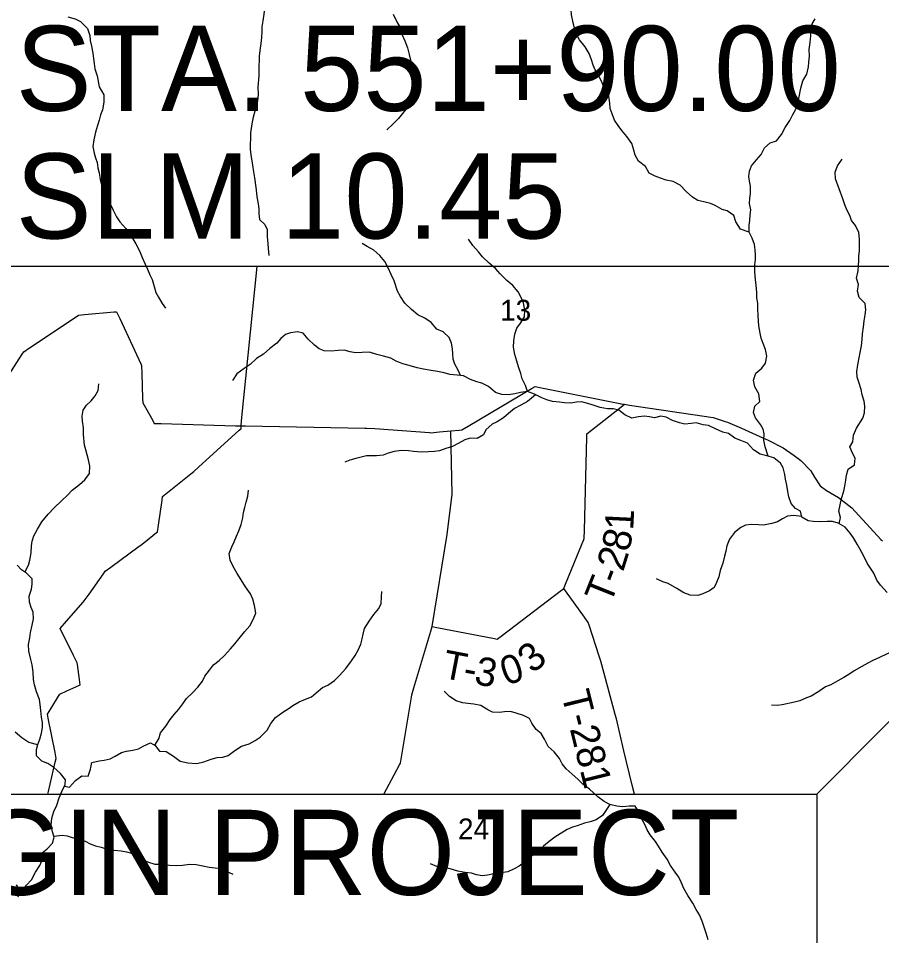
# Model space of a CAD drawing. Extents: x 0 to 34, y 0 to 22.
# Drawn here: x 3.195 to 4.921, y 16.276 to 18.109 of the extents above; entities that cross this region are included whole.
import ezdxf

# ---------------------------------------------------------------- set-up
doc = ezdxf.new("R2010")
doc.units = 0
for name, color, linetype in [('GM_X_County_Road', 7, 'Continuous'), ('GM_X_Minor_River', 7, 'Continuous'), ('GM_X_Section_Text', 7, 'Continuous'), ('GM_X_Township_Road', 7, 'Continuous'), ('GM_X_Township_Road_Text', 7, 'Continuous'), ('SH_Text', 7, 'Continuous')]:
    doc.layers.add(name, color=color, linetype=linetype)

msp = doc.modelspace()

# ---------------------------------------------------------------- linework, layer by layer
at = {"layer": 'GM_X_County_Road'}
msp.add_lwpolyline([(3.2543, 16.5585), (3.2555, 16.5637), (3.269, 16.6223), (3.2708, 16.6302), (3.2685, 16.6419), (3.2548, 16.7107), (3.2533, 16.7184), (3.2598, 16.7288), (3.2757, 16.7543), (3.2784, 16.7586), (3.292, 16.7648), (3.3102, 16.7731), (3.3186, 16.7769), (3.3172, 16.7877), (3.3133, 16.8175), (3.3129, 16.8209), (3.3054, 16.8357), (3.2785, 16.8894), (3.2914, 16.9045), (3.3246, 16.9421), (3.3269, 16.9447), (3.3365, 16.9582), (3.3655, 16.999), (3.369, 17.004), (3.3802, 17.0123), (3.4366, 17.054), (3.44, 17.0564), (3.4524, 17.0663), (3.4681, 17.0788), (3.4733, 17.083), (3.4753, 17.0962), (3.4825, 17.1458), (3.4836, 17.1533), (3.4933, 17.1611), (3.5402, 17.1987), (3.5462, 17.2034), (3.5553, 17.2118), (3.6367, 17.2861), (3.6403, 17.2893), (3.6407, 17.2946), (3.6415, 17.3045), (3.6723, 17.6129)], dxfattribs=at)
at = {"layer": 'GM_X_Minor_River'}
for points in [[(3.6962, 18.2358), (3.6942, 18.2156), (3.694, 18.1932), (3.6925, 18.1838), (3.692, 18.1739), (3.6931, 18.1637), (3.693, 18.1542), (3.6888, 18.1402), (3.6872, 18.1292), (3.6856, 18.1167), (3.6836, 18.1034), (3.682, 18.092), (3.6816, 18.0826), (3.6815, 18.0701), (3.6799, 18.0583), (3.6779, 18.0443), (3.6767, 18.0333), (3.6766, 18.0238), (3.6762, 18.0143), (3.676, 17.9939), (3.6736, 17.9711)], [(4.3661, 17.9698), (4.3612, 17.983), (4.3556, 17.9929), (4.3485, 18.0058), (4.344, 18.0153), (4.3407, 18.0256), (4.3362, 18.0385), (4.3284, 18.0515), (4.3167, 18.0656), (4.3119, 18.0755), (4.3067, 18.0888), (4.3038, 18.1028), (4.3008, 18.1154), (4.3005, 18.1248), (4.2994, 18.1358), (4.2995, 18.1487), (4.3008, 18.1616), (4.3035, 18.1749)], [(3.2943, 18.1116), (3.3086, 18.1074), (3.3196, 18.1024), (3.3335, 18.0886), (3.3379, 18.0742), (3.339, 18.0643), (3.3412, 18.0529), (3.3441, 18.0393), (3.3456, 18.0286), (3.3466, 18.0184), (3.3481, 18.0078), (3.3529, 17.9941), (3.3566, 17.9717)], [(3.9444, 18.1173), (3.9522, 18.1005), (3.9582, 18.0906), (3.9619, 18.0773), (3.9675, 18.0637), (3.9734, 18.0496), (3.9764, 18.0363), (3.9793, 18.0253), (3.9815, 18.0158), (3.9871, 18.0021), (3.9935, 17.9884), (3.9902, 17.9705)], [(4.7596, 17.969), (4.7635, 17.9837), (4.7715, 17.9973), (4.775, 18.0117), (4.7754, 18.0212), (4.7767, 18.033), (4.7764, 18.0462), (4.778, 18.0603), (4.7792, 18.0735), (4.7789, 18.0868), (4.782, 18.0974), (4.7881, 18.1076)], [(3.3566, 17.9717), (3.3662, 17.9558), (3.3662, 17.9414), (3.3631, 17.9259), (3.3597, 17.9157), (3.3566, 17.9054), (3.3531, 17.8945), (3.3497, 17.8812), (3.3462, 17.866), (3.3439, 17.8528), (3.3469, 17.8395), (3.3495, 17.83), (3.3525, 17.8205), (3.3543, 17.8099), (3.3566, 17.8), (3.3588, 17.7868), (3.3614, 17.7769), (3.3648, 17.7674), (3.3697, 17.7572), (3.3742, 17.7477), (3.3847, 17.7256), (3.3914, 17.712), (3.3978, 17.7021), (3.4103, 17.6888), (3.4178, 17.6778), (3.4238, 17.6679), (3.4298, 17.6584), (3.4377, 17.644), (3.4426, 17.631), (3.4486, 17.6174), (3.4531, 17.6075), (3.4583, 17.5961), (3.4625, 17.5866), (3.4666, 17.573), (3.4703, 17.5608), (3.4756, 17.5513), (3.4827, 17.5392), (3.4895, 17.5297)], [(3.6736, 17.9711), (3.6749, 17.9566), (3.6734, 17.9437), (3.6711, 17.9338), (3.668, 17.9229), (3.6649, 17.9111), (3.6622, 17.8979), (3.6595, 17.8801), (3.6591, 17.8672), (3.6587, 17.8577), (3.6586, 17.8471), (3.6597, 17.8361), (3.6634, 17.8156), (3.6653, 17.802), (3.6671, 17.7902), (3.6704, 17.7663), (3.6719, 17.7519), (3.6745, 17.7382), (3.676, 17.728), (3.6759, 17.7185), (3.677, 17.7068), (3.6876, 17.6965), (3.6925, 17.6866), (3.6928, 17.6722), (3.6939, 17.6586), (3.6946, 17.6487), (3.6961, 17.6351)], [(3.9902, 17.9705), (3.9851, 17.9513), (3.9775, 17.9384), (3.971, 17.9286), (3.9634, 17.9188), (3.9551, 17.9089), (3.9448, 17.8976), (3.9319, 17.8859)], [(4.6563, 17.6816), (4.639, 17.6877), (4.6296, 17.7022), (4.6254, 17.7147), (4.6122, 17.7242), (4.6024, 17.7265), (4.5884, 17.7349), (4.5786, 17.7387), (4.5658, 17.7422), (4.5537, 17.7445), (4.5427, 17.7514), (4.5299, 17.7624), (4.5182, 17.7754), (4.5043, 17.7826), (4.4899, 17.7857), (4.4786, 17.7891), (4.468, 17.7934), (4.4559, 17.7995), (4.4488, 17.8128), (4.4348, 17.823), (4.428, 17.8356), (4.4258, 17.8451), (4.4217, 17.8587), (4.4119, 17.8728), (4.4014, 17.8846), (4.3942, 17.8945), (4.3867, 17.9051), (4.3822, 17.9176), (4.3784, 17.9283), (4.3773, 17.9389), (4.3755, 17.9529), (4.3661, 17.9698)], [(4.6942, 17.2341), (4.688, 17.2524), (4.6854, 17.266), (4.6859, 17.2785), (4.684, 17.288), (4.6787, 17.2975), (4.6686, 17.3108), (4.6648, 17.3214), (4.6675, 17.3339), (4.6774, 17.3434), (4.6752, 17.3582), (4.6673, 17.3722), (4.6647, 17.3855), (4.6697, 17.3999), (4.6814, 17.4097), (4.689, 17.4195), (4.6914, 17.4339), (4.6891, 17.4472), (4.6843, 17.4593), (4.6801, 17.4696), (4.6779, 17.4795), (4.6757, 17.4943), (4.675, 17.5041), (4.6743, 17.5143), (4.6736, 17.5291), (4.6732, 17.5397), (4.6717, 17.55), (4.6714, 17.561), (4.6703, 17.5754), (4.6688, 17.5868), (4.6674, 17.6023), (4.6678, 17.616), (4.669, 17.6266), (4.6687, 17.636), (4.6679, 17.6463), (4.6668, 17.6569), (4.6623, 17.6694), (4.6563, 17.6816), (4.6564, 17.6952), (4.6572, 17.7047), (4.658, 17.7161), (4.6595, 17.7259), (4.6569, 17.7388), (4.6573, 17.7494), (4.6585, 17.7589), (4.6586, 17.7733), (4.6567, 17.7832), (4.6556, 17.7927), (4.6568, 17.8036), (4.6606, 17.8139), (4.6709, 17.826), (4.68, 17.8365), (4.6865, 17.8502), (4.6982, 17.86), (4.7107, 17.8641), (4.721, 17.8766), (4.7279, 17.8906), (4.7377, 17.9045), (4.7427, 17.9151), (4.7492, 17.9273), (4.753, 17.9371), (4.7557, 17.9488), (4.7596, 17.969)], [(4.8361, 17.0989), (4.8388, 17.1112), (4.8355, 17.1241), (4.8378, 17.1369), (4.8405, 17.1494), (4.8451, 17.1638), (4.8474, 17.1737), (4.8497, 17.1862), (4.8505, 17.196), (4.8543, 17.2078), (4.8665, 17.2168), (4.868, 17.2297), (4.8624, 17.2396), (4.8575, 17.2529), (4.8636, 17.2627), (4.8648, 17.2759), (4.8709, 17.2896), (4.8831, 17.31), (4.8865, 17.3202), (4.8873, 17.3339), (4.8862, 17.3441), (4.8821, 17.3562), (4.8799, 17.3672), (4.8754, 17.3817), (4.872, 17.3919), (4.8713, 17.4029), (4.8736, 17.4166), (4.876, 17.4306), (4.8783, 17.4412), (4.8806, 17.4544), (4.8818, 17.4669), (4.8826, 17.4783), (4.8849, 17.4919), (4.8861, 17.5041), (4.888, 17.5166), (4.8892, 17.526), (4.8881, 17.5389), (4.876, 17.5511), (4.8727, 17.5636), (4.875, 17.5769), (4.8709, 17.5898), (4.8743, 17.6042), (4.8747, 17.6152), (4.8752, 17.6247), (4.8756, 17.6345), (4.8767, 17.6444), (4.8768, 17.6546), (4.8765, 17.6682), (4.8757, 17.6808), (4.869, 17.6948), (4.8607, 17.7051), (4.8573, 17.7146), (4.8521, 17.7248), (4.8476, 17.7358), (4.8431, 17.748), (4.8285, 17.7878), (4.8278, 17.8011), (4.8327, 17.814), (4.8419, 17.8272)], [(4.2133, 17.3633), (4.2092, 17.3751), (4.2021, 17.3887), (4.1994, 17.3993), (4.1953, 17.4126), (4.1916, 17.424), (4.1875, 17.4369), (4.1849, 17.4517), (4.1857, 17.4642), (4.188, 17.4775), (4.1915, 17.49), (4.1987, 17.4998), (4.2067, 17.5123), (4.2079, 17.5259), (4.2049, 17.54), (4.2008, 17.5498), (4.1944, 17.562), (4.1838, 17.5749), (4.1714, 17.5848), (4.1582, 17.5985), (4.1491, 17.6088), (4.1363, 17.6194), (4.1231, 17.6324), (4.1152, 17.6419), (4.1035, 17.6548), (4.0953, 17.6677)], [(4.0792, 17.395), (4.0746, 17.4055), (4.0675, 17.418), (4.0645, 17.4279), (4.0638, 17.4385), (4.0634, 17.4484), (4.0612, 17.4594), (4.0567, 17.4711), (4.0443, 17.4822), (4.0318, 17.4875), (4.0205, 17.5008), (4.0081, 17.5096), (3.9941, 17.5161), (3.9813, 17.5271), (3.9681, 17.5393), (3.9594, 17.553), (3.9534, 17.5636), (3.9467, 17.5841), (3.9407, 17.597), (3.9347, 17.6103), (3.9279, 17.6228), (3.9181, 17.6346), (3.9057, 17.6453), (3.8925, 17.6529), (3.8826, 17.6586)], [(4.0723, 17.3956), (4.0576, 17.3968), (4.0466, 17.4007), (4.033, 17.4034), (4.0202, 17.4053), (4.005, 17.408), (3.9922, 17.4107), (3.9763, 17.4153), (3.9635, 17.4184), (3.9506, 17.4238), (3.9397, 17.4295), (3.9249, 17.4337), (3.9121, 17.4368), (3.897, 17.4414), (3.8826, 17.4411), (3.8694, 17.4407), (3.8584, 17.4427), (3.8467, 17.4454), (3.8342, 17.445), (3.8206, 17.4436), (3.8066, 17.4444), (3.7967, 17.4486), (3.7869, 17.4554), (3.7745, 17.4676), (3.7647, 17.4798), (3.753, 17.4821), (3.7394, 17.4806), (3.7295, 17.4772), (3.72, 17.4693), (3.7121, 17.4595), (3.6976, 17.4489), (3.6851, 17.438), (3.6715, 17.4293), (3.6589, 17.4172), (3.6464, 17.4093), (3.632, 17.3984), (3.6233, 17.3851)], [(4.9321, 16.9618), (4.9185, 16.9763), (4.9114, 16.9862), (4.9054, 17.0002), (4.899, 17.0101), (4.8922, 17.0204), (4.8855, 17.034), (4.8776, 17.0485), (4.8719, 17.0583), (4.8644, 17.0705), (4.858, 17.08), (4.8478, 17.0922), (4.8339, 17.1002), (4.8225, 17.1036), (4.8119, 17.1033), (4.7968, 17.103), (4.784, 17.1034), (4.7741, 17.1046), (4.7617, 17.1118), (4.7587, 17.1243), (4.7489, 17.1297), (4.7402, 17.1396), (4.7357, 17.1525), (4.7335, 17.1635), (4.7313, 17.176), (4.729, 17.1881), (4.7272, 17.1976), (4.7238, 17.2105), (4.7189, 17.22), (4.7054, 17.2307), (4.6914, 17.2349), (4.6778, 17.238), (4.6649, 17.2464), (4.6529, 17.2601), (4.6397, 17.2654), (4.6272, 17.27), (4.6151, 17.2792), (4.6038, 17.2822), (4.5891, 17.2887), (4.5747, 17.2949), (4.5645, 17.2964), (4.5505, 17.3003), (4.5403, 17.2995), (4.5274, 17.2981), (4.5172, 17.3008), (4.5032, 17.305), (4.49, 17.3119), (4.4798, 17.3138), (4.467, 17.3108), (4.4571, 17.3127), (4.4469, 17.3139), (4.4352, 17.3124), (4.4219, 17.3098), (4.4076, 17.3163), (4.3955, 17.3258), (4.3842, 17.3282), (4.3728, 17.3286), (4.3581, 17.3313), (4.3445, 17.3355), (4.3339, 17.339), (4.3207, 17.3424), (4.3108, 17.3417), (4.2995, 17.3395), (4.287, 17.3403), (4.2772, 17.3418), (4.2628, 17.343), (4.2518, 17.3465), (4.2416, 17.3507), (4.2273, 17.3575), (4.2133, 17.3633), (4.1989, 17.3614), (4.1876, 17.3585), (4.1747, 17.3562), (4.1615, 17.357), (4.149, 17.3609), (4.135, 17.373), (4.1218, 17.3795), (4.112, 17.3826), (4.0988, 17.3872), (4.0848, 17.3945), (4.0723, 17.3956)], [(3.2084, 17.0023), (3.2152, 17.0163), (3.2183, 17.0261), (3.221, 17.0409), (3.2218, 17.0545), (3.223, 17.064), (3.2264, 17.0746), (3.2333, 17.0882), (3.2424, 17.1026), (3.2546, 17.1181), (3.2671, 17.1306), (3.2815, 17.1445), (3.2937, 17.1559), (3.3028, 17.1657), (3.3176, 17.177), (3.3278, 17.1868), (3.3377, 17.1993), (3.3381, 17.2141), (3.3352, 17.2266), (3.3326, 17.2368), (3.3303, 17.2463), (3.3277, 17.2562), (3.3255, 17.2774), (3.3256, 17.2907), (3.3233, 17.304), (3.323, 17.3138), (3.3246, 17.326), (3.3314, 17.3358), (3.3409, 17.3445), (3.3489, 17.3547), (3.3546, 17.3653), (3.3562, 17.3785)], [(4.229, 17.3567), (4.2132, 17.3432), (4.2, 17.336), (4.1871, 17.3293), (4.1753, 17.3191), (4.1651, 17.3108), (4.1522, 17.3025), (4.1423, 17.298), (4.1298, 17.2866), (4.1252, 17.2764), (4.1123, 17.2693), (4.0987, 17.2701), (4.0877, 17.2667), (4.0741, 17.2592), (4.0631, 17.2535), (4.0498, 17.249), (4.0373, 17.2445), (4.0271, 17.243), (4.015, 17.2423), (4.001, 17.242), (3.9851, 17.2432), (3.9749, 17.2447), (3.9613, 17.2452), (3.9465, 17.243), (3.9344, 17.2396), (3.9246, 17.2362), (3.911, 17.2347), (3.9007, 17.2344), (3.8909, 17.2344), (3.8807, 17.2318), (3.8701, 17.2296), (3.8576, 17.2258), (3.8477, 17.2217)], [(3.4677, 16.6566), (3.4757, 16.6692), (3.4796, 16.6814), (3.4898, 16.6946), (3.4989, 16.7078), (3.5069, 16.7176), (3.516, 16.7286), (3.524, 16.7392), (3.5313, 16.7498), (3.5434, 16.7611), (3.5537, 16.7724), (3.5635, 16.7845), (3.5681, 16.7944), (3.5772, 16.8065), (3.5856, 16.8167), (3.5966, 16.8257), (3.6072, 16.8359), (3.619, 16.8492), (3.6277, 16.859), (3.6369, 16.8696), (3.6471, 16.8828), (3.6581, 16.8949), (3.6646, 16.9074), (3.6696, 16.9202), (3.667, 16.9358), (3.664, 16.9479), (3.6595, 16.9586), (3.649, 16.9726), (3.6403, 16.9867), (3.6328, 16.9996), (3.6245, 17.0136), (3.6185, 17.0262), (3.6167, 17.0395), (3.6217, 17.0531), (3.6266, 17.0629), (3.6316, 17.0743), (3.6361, 17.0849), (3.6404, 17.0974), (3.6438, 17.111), (3.645, 17.1212), (3.6477, 17.1314), (3.6507, 17.1421), (3.6542, 17.1538), (3.655, 17.1663)], [(4.7613, 17.1133), (4.745, 17.1157), (4.7325, 17.1138), (4.7231, 17.1086), (4.7125, 17.1029), (4.7015, 17.0992), (4.6848, 17.0962), (4.6746, 17.0966), (4.6599, 17.0974), (4.6489, 17.0959), (4.6394, 17.0914), (4.6265, 17.0812), (4.617, 17.068), (4.6116, 17.0548), (4.6093, 17.0438), (4.6067, 17.0339), (4.6032, 17.0199), (4.5982, 17.0055), (4.5952, 16.9927), (4.591, 16.9817), (4.5864, 16.9715), (4.5769, 16.9647), (4.5636, 16.959), (4.5534, 16.9557), (4.5383, 16.9565), (4.5254, 16.9607), (4.5118, 16.9698), (4.4941, 16.9798), (4.4835, 16.9828), (4.4707, 16.9886)], [(3.1942, 16.3534), (3.2045, 16.3666), (3.2113, 16.3765), (3.2212, 16.3878), (3.2292, 16.4029), (3.238, 16.4158), (3.2437, 16.429), (3.243, 16.4412), (3.2525, 16.4491), (3.2635, 16.4604), (3.2666, 16.4725), (3.2636, 16.4831), (3.261, 16.4968), (3.2622, 16.5104), (3.2664, 16.5237), (3.2721, 16.5369), (3.2767, 16.5513), (3.2824, 16.5638), (3.2889, 16.5778), (3.2893, 16.5873), (3.2795, 16.5998), (3.2663, 16.612), (3.2539, 16.6196), (3.2418, 16.6246), (3.2316, 16.6353), (3.2316, 16.6478), (3.234, 16.6576), (3.2378, 16.6686), (3.2412, 16.6803), (3.2435, 16.6921), (3.2432, 16.7019), (3.2417, 16.7126), (3.2403, 16.7255), (3.2388, 16.7376), (3.2373, 16.7475), (3.2317, 16.7634), (3.2276, 16.7771), (3.2254, 16.7877), (3.225, 16.8032), (3.2228, 16.8169), (3.2202, 16.8275), (3.2161, 16.8446), (3.2158, 16.8578), (3.2181, 16.8711), (3.2196, 16.8817), (3.2231, 16.8961), (3.2258, 16.909), (3.2247, 16.9222), (3.221, 16.9317), (3.2172, 16.942), (3.2169, 16.9545), (3.2215, 16.9685), (3.223, 16.978), (3.2231, 16.989), (3.2114, 17.0004), (3.2016, 17.0069), (3.1925, 17.0164)], [(3.2874, 16.5745), (3.2972, 16.5729), (3.3093, 16.5857), (3.3222, 16.5951), (3.3347, 16.5947), (3.3397, 16.6087), (3.3424, 16.6216), (3.3568, 16.625), (3.3666, 16.6264), (3.3784, 16.6294), (3.389, 16.6343), (3.4011, 16.6422), (3.4117, 16.6445), (3.4238, 16.6463), (3.4355, 16.6489), (3.445, 16.6546), (3.4591, 16.6613), (3.4689, 16.656), (3.4775, 16.6446), (3.4908, 16.6442), (3.5055, 16.6343), (3.5187, 16.6247), (3.5342, 16.6209), (3.552, 16.6201), (3.5663, 16.623), (3.5804, 16.6287), (3.5929, 16.6317), (3.6042, 16.6324), (3.6148, 16.6358), (3.6277, 16.6456), (3.641, 16.6542), (3.6565, 16.6591), (3.6683, 16.6659), (3.6785, 16.6723), (3.6925, 16.6866), (3.7002, 16.6999), (3.7093, 16.712), (3.7241, 16.7225), (3.7343, 16.7293), (3.7442, 16.7361), (3.7563, 16.7429), (3.7692, 16.7482), (3.7809, 16.7534), (3.7908, 16.7613), (3.8029, 16.7715), (3.8139, 16.7764), (3.8272, 16.7855), (3.8371, 16.796), (3.8496, 16.81), (3.8614, 16.8251), (3.8682, 16.8354), (3.8743, 16.846), (3.8801, 16.8581), (3.8827, 16.8687), (3.8843, 16.8785), (3.8874, 16.8899), (3.8965, 16.9042), (3.906, 16.9175), (3.9155, 16.9296), (3.9205, 16.9394), (3.9213, 16.9531), (3.9217, 16.9633)], [(4.9687, 16.8454), (4.9574, 16.8465), (4.9434, 16.8439), (4.9305, 16.8386), (4.9169, 16.8319), (4.9032, 16.8255), (4.8934, 16.8202), (4.8812, 16.8134), (4.8661, 16.8048), (4.8555, 16.798), (4.8456, 16.7916), (4.8331, 16.7852), (4.8191, 16.7773), (4.8088, 16.7731), (4.7956, 16.7637), (4.78, 16.7547), (4.7705, 16.7509), (4.7577, 16.7449), (4.7467, 16.7427), (4.7221, 16.7371), (4.7119, 16.736), (4.7005, 16.7364)], [(4.5739, 16.2676), (4.5702, 16.2812), (4.5661, 16.293), (4.5623, 16.3048), (4.5567, 16.3177), (4.55, 16.3283), (4.5432, 16.3409), (4.5338, 16.356), (4.5255, 16.3701), (4.5199, 16.3826), (4.5154, 16.3925), (4.5082, 16.4031), (4.4992, 16.4161), (4.4921, 16.4286), (4.4819, 16.4427), (4.4751, 16.4548), (4.4691, 16.4643), (4.4582, 16.4776), (4.4522, 16.4875), (4.4481, 16.497), (4.4405, 16.5111), (4.4353, 16.5232), (4.4285, 16.5346), (4.416, 16.5346), (4.4036, 16.5336), (4.3915, 16.5347), (4.3778, 16.5382), (4.3665, 16.5443), (4.3533, 16.5535), (4.3367, 16.5683), (4.3239, 16.5786), (4.3133, 16.5885), (4.302, 16.5988), (4.29, 16.609), (4.2824, 16.6193), (4.2768, 16.6296), (4.2663, 16.6429), (4.2546, 16.6539), (4.2467, 16.6683), (4.2403, 16.6801), (4.2301, 16.6881), (4.2215, 16.7006), (4.2169, 16.7101), (4.2052, 16.7159), (4.1905, 16.7205), (4.1788, 16.7235), (4.1667, 16.7232), (4.1565, 16.7217), (4.1432, 16.7225), (4.1334, 16.7271), (4.1194, 16.7359), (4.1058, 16.7382), (4.0937, 16.7398), (4.0828, 16.741), (4.0707, 16.7448), (4.0571, 16.7536), (4.0465, 16.7642)], [(3.2339, 16.6575), (3.2162, 16.6619), (3.2022, 16.671), (3.1886, 16.6824)], [(4.3778, 16.5382), (4.363, 16.5163), (4.3501, 16.5072), (4.338, 16.5031), (4.327, 16.5005), (4.3126, 16.4956), (4.3028, 16.4926), (4.2922, 16.4877), (4.2781, 16.4791), (4.2679, 16.4726), (4.2561, 16.464), (4.2448, 16.4545), (4.2315, 16.4425), (4.2201, 16.4338), (4.2095, 16.4247), (4.1962, 16.4149), (4.1863, 16.4093), (4.1734, 16.4033), (4.1602, 16.4014), (4.1458, 16.3996), (4.1329, 16.3966), (4.1223, 16.3955), (4.111, 16.3974), (4.1012, 16.4005), (4.0887, 16.402), (4.074, 16.4048), (4.0581, 16.4097), (4.0456, 16.4121), (4.0316, 16.4144), (4.0192, 16.4194)], [(3.2659, 16.4748), (3.2825, 16.4766), (3.2927, 16.4751), (3.3029, 16.472), (3.3157, 16.4686), (3.3286, 16.4647), (3.3388, 16.4594), (3.3493, 16.4555), (3.3607, 16.4525), (3.3709, 16.4494), (3.3868, 16.4467), (3.4008, 16.4455), (3.4113, 16.4432), (3.4212, 16.4405), (3.4347, 16.4329), (3.4446, 16.4271), (3.4555, 16.4226), (3.468, 16.4187), (3.4831, 16.4187), (3.4975, 16.4167), (3.5111, 16.4163), (3.5236, 16.4166), (3.5376, 16.4185), (3.5508, 16.4184), (3.5641, 16.4157), (3.5769, 16.4126), (3.5886, 16.4114), (3.5985, 16.4103), (3.6109, 16.4045), (3.6238, 16.3988)], [(3.2013, 16.3626), (3.1913, 16.3777)]]:
    msp.add_lwpolyline(points, dxfattribs=at)
at = {"layer": 'GM_X_Township_Road'}
msp.add_line((4.4267, 16.5585), (4.4222, 16.5769), dxfattribs=at)
for points in [[(3.1706, 17.3877), (3.2028, 17.4379), (3.2059, 17.4427), (3.2177, 17.4506), (3.3088, 17.5112), (3.3155, 17.5156), (3.3273, 17.5167), (3.3867, 17.5221), (3.3914, 17.5225), (3.3978, 17.5087), (3.4398, 17.4186), (3.4415, 17.415), (3.442, 17.3991), (3.4435, 17.3494), (3.4437, 17.3405), (3.4492, 17.3309), (3.4638, 17.305), (3.4669, 17.2995), (3.4805, 17.2991), (3.6296, 17.2948), (3.6372, 17.2946), (3.6407, 17.2946), (3.6495, 17.2944), (3.8881, 17.2902), (3.8921, 17.2901), (3.9079, 17.2889), (4.017, 17.2809), (4.02, 17.2806), (4.0368, 17.2823), (4.06, 17.2846), (4.0764, 17.2862), (4.0818, 17.2867), (4.0942, 17.2941), (4.2226, 17.37), (4.2282, 17.3733), (4.2413, 17.3707), (4.3973, 17.3393), (4.3997, 17.3388), (4.4071, 17.3375), (4.4168, 17.3357), (4.5842, 17.3114), (4.6081, 17.3033)], [(4.2863, 16.9716), (4.2905, 16.9816), (4.3116, 17.0333), (4.3257, 17.0677), (4.3265, 17.0695), (4.3269, 17.0861), (4.3313, 17.272), (4.3314, 17.2784), (4.3411, 17.2859), (4.3997, 17.3317), (4.4071, 17.3375)], [(4.6081, 17.3033), (4.6129, 17.3016), (4.6411, 17.2899), (4.6851, 17.2702), (4.6894, 17.2681)], [(4.0226, 16.8936), (4.0525, 17.0776), (4.0621, 17.1581), (4.06, 17.2846)], [(4.6894, 17.2681), (4.6929, 17.2663), (4.7243, 17.2506), (4.7462, 17.2353), (4.7596, 17.2255), (4.7792, 17.2047), (4.787, 17.1922), (4.7981, 17.1744), (4.8106, 17.1651), (4.8345, 17.1514), (4.8615, 17.131), (4.9192, 17.0675), (4.9224, 17.065)], [(4.4222, 16.5769), (4.4057, 16.6451), (4.391, 16.709), (4.3885, 16.718), (4.3615, 16.8167), (4.3595, 16.8241), (4.3562, 16.8344), (4.3361, 16.8964), (4.3345, 16.9016), (4.3268, 16.9122), (4.2888, 16.9651), (4.2855, 16.9696), (4.2863, 16.9716)], [(4.0226, 16.8936), (4.0315, 16.8919), (4.1473, 16.8696), (4.1527, 16.8685), (4.1628, 16.8762), (4.2783, 16.9641), (4.2855, 16.9696)], [(3.9261, 16.5585), (3.9574, 16.6174), (3.9593, 16.6208), (3.9618, 16.6363), (3.981, 16.7525), (3.9817, 16.7568), (3.986, 16.7714), (4.0198, 16.8841), (4.0226, 16.8936)]]:
    msp.add_lwpolyline(points, dxfattribs=at)
at = {"layer": 'SH_Text'}
for points in [[(3.1565, 18.3776), (4.9408, 18.3776), (4.9408, 17.6129), (3.1565, 17.6129)], [(4.7911, 16.5585), (4.7911, 15.8085), (5.3209, 17.091)], [(2.7795, 16.5585), (4.7911, 16.5585), (4.7911, 15.8085), (2.7795, 15.8085)]]:
    msp.add_lwpolyline(points, close=True, dxfattribs=at)

# ---------------------------------------------------------------- texts
at = {"layer": 'GM_X_Section_Text'}
for s, p in [('13', (4.1582, 17.5045)), ('24', (4.074, 16.4682))]:
    msp.add_text(s, height=0.04186, rotation=0, dxfattribs=at).set_placement(p)
at = {"layer": 'GM_X_Township_Road_Text'}
for s, height, rotation, p in [('1', 0.0568, 87.2046, (4.4243, 17.0849)), ('8', 0.0568, 78.5524, (4.4162, 17.0413)), ('2', 0.0568, 72.6804, (4.4042, 17.0017)), ('T', 0.0568, 68.0569, (4.3784, 16.9358)), ('-', 0.0568, 69.1535, (4.3947, 16.9763)), ('T', 0.0568, 349.104, (4.0401, 16.7916)), ('3', 0.0568, 40.9649, (4.2237, 16.798)), ('3', 0.0568, 349.1052, (4.1045, 16.7792)), ('0', 0.0568, 19.1006, (4.1705, 16.7749)), ('-', 0.0568, 349.1042, (4.0818, 16.7836)), ('T-281', 0.05682, 283.8383, (4.2802, 16.7591))]:
    msp.add_text(s, height=height, rotation=rotation, dxfattribs=at).set_placement(p)
at = {"layer": 'SH_Text'}
for s, p in [('STA. 551+90.00', (3.1899, 17.9238)), ('SLM 10.45', (3.1899, 17.6688)), ('BEGIN PROJECT', (2.8051, 16.3574))]:
    msp.add_text(s, height=0.17, dxfattribs=at).set_placement(p)

doc.saveas('drawing.dxf')
